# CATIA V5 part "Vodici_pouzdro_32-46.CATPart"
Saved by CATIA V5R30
Part number: Vodici_pouzdro_32-46
Definition: E 1100_32-46_2
Nomenclature: E 1100_32-46_2
Source: Unknown
Description: PART--DESC
Bounding box of the stored display mesh (mm): x -210.3 to -163.7, y -160.3 to -113.7, z -101 to -46
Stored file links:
  E:\Bakalarka\Model\Forma_v7\Vodici_pouzdro_32-46.CATPart
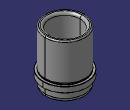
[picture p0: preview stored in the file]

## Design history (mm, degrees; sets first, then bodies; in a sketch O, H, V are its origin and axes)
Body1 "MANIFOLD_SOLID_BREP #3914" (main body)
  Solid1: solid without history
